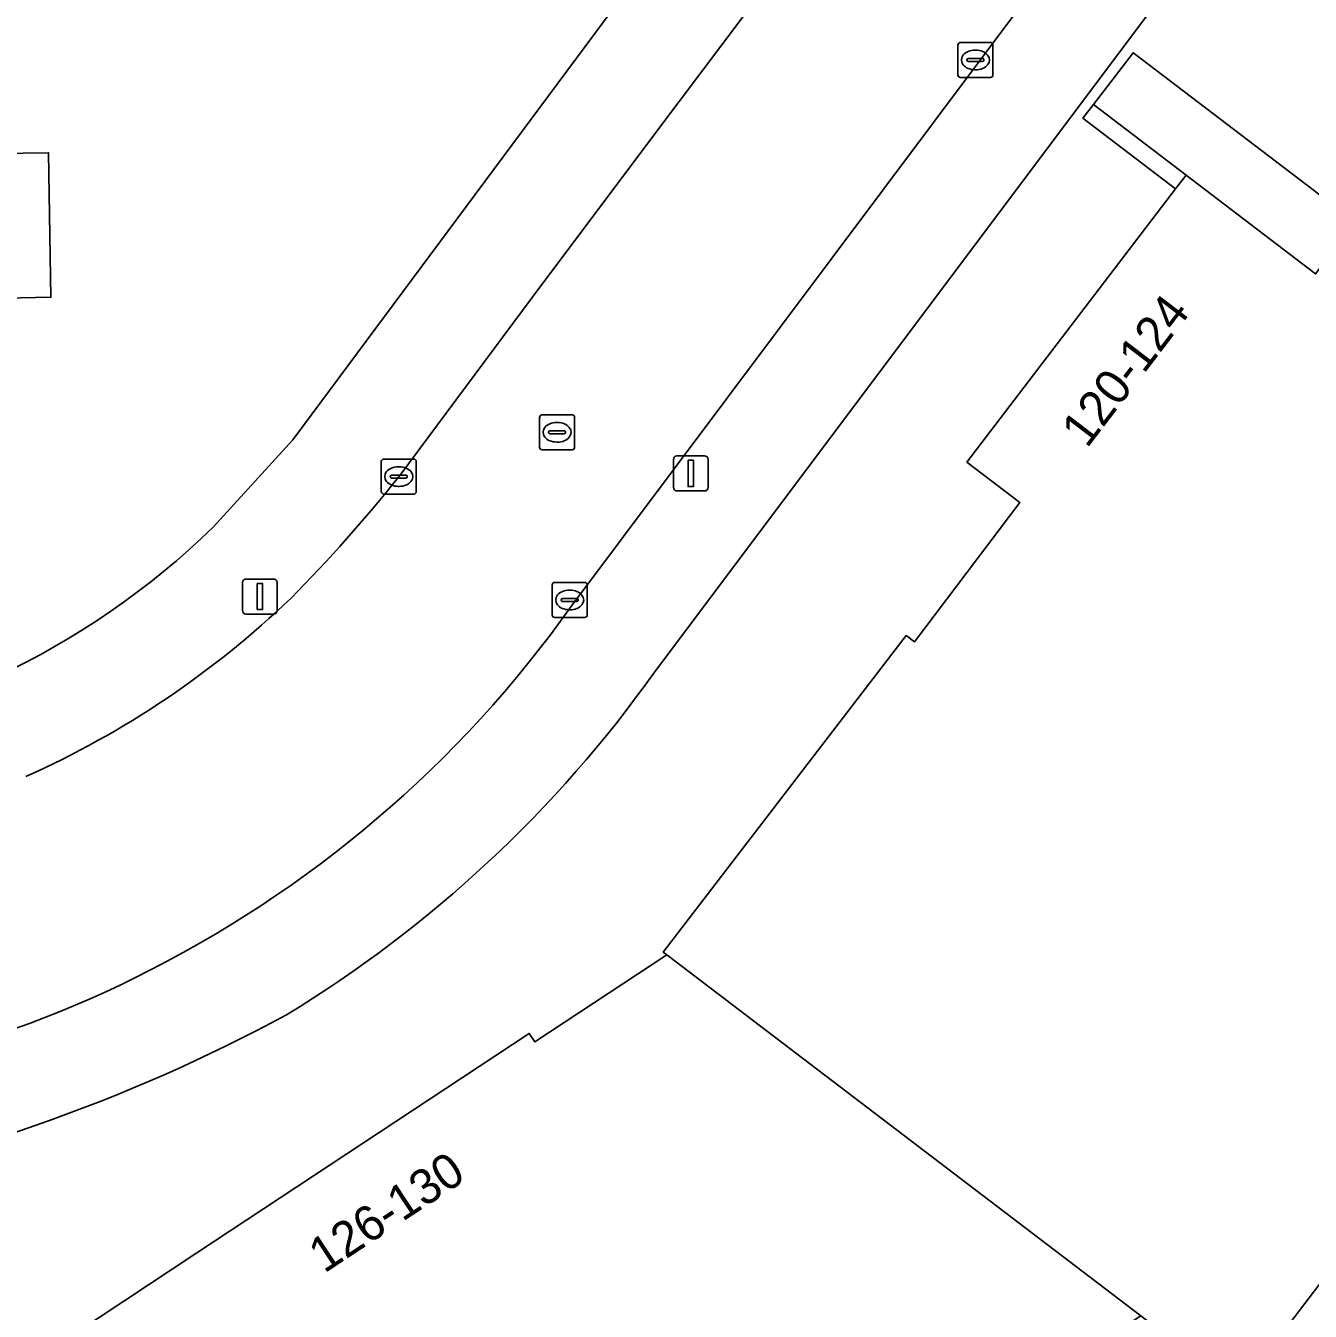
# Model space of a CAD drawing. Extents: x 161139 to 161601, y 381708 to 382245.
# Drawn here: x 161337.13 to 161373.8, y 381862.38 to 381899.09 of the extents above; entities that cross this region are included whole.
import ezdxf

# ---------------------------------------------------------------- set-up
doc = ezdxf.new("R2010")
doc.units = 0
for name, color, linetype in [('IMGEO_Erf', 7, 'Continuous'), ('IMGEO_Groenvoorziening', 7, 'Continuous'), ('IMGEO_Hek', 7, 'Continuous'), ('IMGEO_Kolk', 7, 'Continuous'), ('IMGEO_Lichtmast', 7, 'Continuous'), ('IMGEO_Muur', 7, 'Continuous'), ('IMGEO_Pand', 7, 'Continuous'), ('IMGEO_Pand_nummerreeks', 7, 'Continuous'), ('IMGEO_Rijbaan_lokaal_open', 7, 'Continuous'), ('IMGEO_Rioolput', 7, 'Continuous'), ('IMGEO_Voetpad_op_trap', 7, 'Continuous'), ('IMGEO_Voetpad_open', 7, 'Continuous')]:
    doc.layers.add(name, color=color, linetype=linetype)

msp = doc.modelspace()

# ---------------------------------------------------------------- linework, layer by layer
at = {"layer": 'IMGEO_Erf'}
for points in [[(161342.481, 381884.773), (161344.76, 381887.264), (161354.145, 381899.917), (161371.073, 381922.177)], [(161335.385, 381899.929), (161335.401, 381898.908), (161336.27, 381898.922), (161336.325, 381895.438), (161337.781, 381895.461), (161337.847, 381891.334), (161336.547, 381891.313), (161336.619, 381886.808), (161328.732, 381886.683), (161328.661, 381891.157), (161328.032, 381891.147), (161327.967, 381895.237), (161328.465, 381895.244), (161328.41, 381898.782), (161329.29, 381898.8), (161329.269, 381899.821)]]:
    msp.add_lwpolyline(points, dxfattribs=at)
msp.add_arc((161326.709, 381900.982), 22.616, 275.9879, 314.2183, dxfattribs=at)
at = {"layer": 'IMGEO_Groenvoorziening'}
for points in [[(161382.438, 381917.119), (161355.077, 381880.626)], [(161337.847, 381861.294), (161342.013, 381864.045), (161351.507, 381870.313), (161351.666, 381870.071), (161355.437, 381872.558), (161355.333, 381872.637), (161362.266, 381881.673), (161362.5, 381881.493), (161365.51, 381885.478), (161364, 381886.63), (161369.955, 381894.435), (161367.312, 381896.447), (161367.614, 381896.841), (161368.743, 381898.317), (161368.776, 381898.292), (161375.084, 381893.489)]]:
    msp.add_lwpolyline(points, dxfattribs=at)
for centre, radius, start, end in [((161326.096, 381901.218), 35.552, 301.3226, 324.6045), ((161321.407, 381913.724), 48.737, 279.9868, 298.3875)]:
    msp.add_arc(centre, radius, start, end, dxfattribs=at)
at = {"layer": 'IMGEO_Hek'}
for points in [[(161362.5, 381881.493), (161365.51, 381885.478)], [(161351.666, 381870.071), (161355.437, 381872.558)], [(161337.847, 381861.294), (161342.013, 381864.045)]]:
    msp.add_lwpolyline(points, dxfattribs=at)
at = {"layer": 'IMGEO_Kolk'}
for p, q in [((161363.743, 381897.685), (161363.743, 381898.537)), ((161363.818, 381898.611), (161364.67, 381898.611)), ((161364.231, 381898.391), (161364.256, 381898.391)), ((161364.744, 381898.537), (161364.744, 381897.685)), ((161364.002, 381898.105), (161364.002, 381898.117)), ((161364.44, 381898.068), (161364.042, 381898.068)), ((161364.045, 381898.154), (161364.443, 381898.154)), ((161364.486, 381898.117), (161364.486, 381898.105)), ((161364.67, 381897.611), (161363.818, 381897.611)), ((161364.254, 381897.831), (161364.229, 381897.831)), ((161347.28, 381885.789), (161347.28, 381886.641)), ((161347.355, 381886.715), (161348.207, 381886.715)), ((161348.281, 381886.641), (161348.281, 381885.789)), ((161347.539, 381886.209), (161347.539, 381886.221)), ((161347.582, 381886.258), (161347.98, 381886.258)), ((161347.768, 381886.495), (161347.793, 381886.495)), ((161348.023, 381886.221), (161348.023, 381886.209)), ((161347.977, 381886.172), (161347.579, 381886.172)), ((161347.791, 381885.935), (161347.766, 381885.935)), ((161348.207, 381885.715), (161347.355, 381885.715)), ((161352.16, 381882.266), (161352.16, 381883.118)), ((161352.235, 381883.192), (161353.087, 381883.192)), ((161352.648, 381882.972), (161352.673, 381882.972)), ((161353.161, 381883.118), (161353.161, 381882.266)), ((161352.419, 381882.686), (161352.419, 381882.698)), ((161352.857, 381882.649), (161352.459, 381882.649)), ((161352.462, 381882.735), (161352.86, 381882.735)), ((161352.903, 381882.698), (161352.903, 381882.686)), ((161353.087, 381882.192), (161352.235, 381882.192)), ((161352.671, 381882.412), (161352.646, 381882.412))]:
    msp.add_line(p, q, dxfattribs=at)
for points in [[(161363.743, 381897.685), (161363.743, 381898.537)], [(161363.818, 381898.611), (161364.67, 381898.611)], [(161364.744, 381898.537), (161364.744, 381897.685)], [(161364.67, 381897.611), (161363.818, 381897.611)], [(161347.28, 381885.789), (161347.28, 381886.641)], [(161347.355, 381886.715), (161348.207, 381886.715)], [(161348.281, 381886.641), (161348.281, 381885.789)], [(161348.207, 381885.715), (161347.355, 381885.715)], [(161352.16, 381882.266), (161352.16, 381883.118)], [(161352.235, 381883.192), (161353.087, 381883.192)], [(161353.161, 381883.118), (161353.161, 381882.266)], [(161353.087, 381882.192), (161352.235, 381882.192)]]:
    msp.add_lwpolyline(points, dxfattribs=at)
for centre, radius, start, end in [((161363.82, 381898.535), 0.0765, 91.552, 178.448), ((161363.82, 381898.535), 0.0765, 91.552, 178.448), ((161364.668, 381898.535), 0.0765, 1.552, 88.448), ((161364.668, 381898.535), 0.0765, 1.552, 88.448), ((161364.042, 381898.114), 0.0403, 85.8775, 175.7526), ((161364.039, 381898.104), 0.0366, 178.938, 274.7102), ((161364.443, 381898.111), 0.043, 264.8664, 352.4533), ((161364.447, 381898.116), 0.0386, 1.7309, 96.639), ((161363.82, 381897.687), 0.0765, 181.552, 268.448), ((161363.82, 381897.687), 0.0765, 181.552, 268.448), ((161364.668, 381897.687), 0.0765, 271.552, 358.448), ((161364.668, 381897.687), 0.0765, 271.552, 358.448), ((161347.357, 381886.639), 0.0765, 91.552, 178.448), ((161347.357, 381886.639), 0.0765, 91.552, 178.448), ((161348.205, 381886.639), 0.0765, 1.552, 88.448), ((161348.205, 381886.639), 0.0765, 1.552, 88.448), ((161347.579, 381886.218), 0.0403, 85.8775, 175.7526), ((161347.576, 381886.208), 0.0366, 178.938, 274.7102), ((161347.98, 381886.215), 0.043, 264.8664, 352.4533), ((161347.984, 381886.22), 0.0386, 1.7309, 96.639), ((161347.357, 381885.791), 0.0765, 181.552, 268.448), ((161347.357, 381885.791), 0.0765, 181.552, 268.448), ((161348.205, 381885.791), 0.0765, 271.552, 358.448), ((161348.205, 381885.791), 0.0765, 271.552, 358.448), ((161352.237, 381883.116), 0.0765, 91.552, 178.448), ((161352.237, 381883.116), 0.0765, 91.552, 178.448), ((161353.085, 381883.116), 0.0765, 1.552, 88.448), ((161353.085, 381883.116), 0.0765, 1.552, 88.448), ((161352.459, 381882.695), 0.0403, 85.8775, 175.7526), ((161352.456, 381882.685), 0.0366, 178.938, 274.7102), ((161352.86, 381882.692), 0.043, 264.8664, 352.4533), ((161352.864, 381882.697), 0.0386, 1.7309, 96.639), ((161352.237, 381882.268), 0.0765, 181.552, 268.448), ((161352.237, 381882.268), 0.0765, 181.552, 268.448), ((161353.085, 381882.268), 0.0765, 271.552, 358.448), ((161353.085, 381882.268), 0.0765, 271.552, 358.448)]:
    msp.add_arc(centre, radius, start, end, dxfattribs=at)
for centre, major_axis, ratio, start_param, end_param in [((161364.23, 381898.111), (-0.387, 0.002), 0.722429, 4.712389, 7.853982), ((161364.255, 381898.111), (-0.39, 0.002), 0.717154, 1.570796, 4.712389), ((161347.767, 381886.215), (-0.387, 0.002), 0.722429, 4.712389, 7.853982), ((161347.792, 381886.215), (-0.39, 0.002), 0.717154, 1.570796, 4.712389), ((161352.647, 381882.692), (-0.387, 0.002), 0.722429, 4.712389, 7.853982), ((161352.672, 381882.692), (-0.39, 0.002), 0.717154, 1.570796, 4.712389)]:
    msp.add_ellipse(centre, major_axis=major_axis, ratio=ratio, start_param=start_param, end_param=end_param, dxfattribs=at)
at = {"layer": 'IMGEO_Lichtmast'}
for p, q in [((161355.621, 381885.904), (161355.621, 381886.704)), ((161355.621, 381886.704), (161355.621, 381885.904)), ((161355.721, 381886.804), (161356.511, 381886.804)), ((161356.511, 381886.804), (161355.721, 381886.804)), ((161356.611, 381886.704), (161356.611, 381885.904)), ((161356.611, 381885.904), (161356.611, 381886.704)), ((161356.511, 381885.804), (161355.721, 381885.804)), ((161355.721, 381885.804), (161356.511, 381885.804)), ((161343.418, 381883.29), (161344.208, 381883.29)), ((161344.208, 381883.29), (161343.418, 381883.29)), ((161343.318, 381882.39), (161343.318, 381883.19)), ((161343.318, 381883.19), (161343.318, 381882.39)), ((161344.308, 381883.19), (161344.308, 381882.39)), ((161344.308, 381882.39), (161344.308, 381883.19)), ((161344.208, 381882.29), (161343.418, 381882.29)), ((161343.418, 381882.29), (161344.208, 381882.29))]:
    msp.add_line(p, q, dxfattribs=at)
for points in [[(161356.041, 381886.679), (161356.191, 381886.679), (161356.191, 381885.929), (161356.041, 381885.929), (161356.041, 381886.679)], [(161343.738, 381883.165), (161343.888, 381883.165), (161343.888, 381882.415), (161343.738, 381882.415), (161343.738, 381883.165)]]:
    msp.add_lwpolyline(points, dxfattribs=at)
for centre, start, end in [((161355.721, 381886.704), 90, 180), ((161355.721, 381886.704), 90, 180), ((161356.511, 381886.704), 0, 90), ((161356.511, 381886.704), 360, 90), ((161355.721, 381885.904), 180, 270), ((161355.721, 381885.904), 180, 270), ((161356.511, 381885.904), 270, 0), ((161356.511, 381885.904), 270, 0), ((161343.418, 381883.19), 90, 180), ((161343.418, 381883.19), 90, 180), ((161344.208, 381883.19), 0, 90), ((161344.208, 381883.19), 360, 90), ((161343.418, 381882.39), 180, 270), ((161343.418, 381882.39), 180, 270), ((161344.208, 381882.39), 270, 0), ((161344.208, 381882.39), 270, 0)]:
    msp.add_arc(centre, 0.1, start, end, dxfattribs=at)
at = {"layer": 'IMGEO_Muur'}
msp.add_lwpolyline([(161367.614, 381896.841), (161367.312, 381896.447), (161369.955, 381894.435), (161370.262, 381894.819)], close=True, dxfattribs=at)
at = {"layer": 'IMGEO_Pand'}
msp.add_lwpolyline([(161329.269, 381899.821), (161329.29, 381898.8), (161328.41, 381898.782), (161328.465, 381895.244), (161327.967, 381895.237), (161328.032, 381891.147), (161328.661, 381891.157), (161328.732, 381886.683), (161336.619, 381886.808), (161336.547, 381891.313), (161337.847, 381891.334), (161337.781, 381895.461), (161336.325, 381895.438), (161336.27, 381898.922), (161335.401, 381898.908), (161335.385, 381899.929)], dxfattribs=at)
for points in [[(161390.838, 381885.171), (161376.851, 381895.819), (161375.084, 381893.489), (161373.955, 381892.001), (161370.262, 381894.819), (161369.955, 381894.435), (161364, 381886.63), (161365.51, 381885.478), (161362.5, 381881.493), (161362.266, 381881.673), (161355.333, 381872.637), (161355.437, 381872.558), (161368.964, 381862.254), (161371.759, 381860.122), (161374.079, 381863.168), (161378.602, 381869.107), (161378.802, 381869.369), (161381.677, 381873.144)], [(161355.437, 381872.558), (161351.666, 381870.071), (161351.507, 381870.313), (161342.013, 381864.045), (161337.847, 381861.294), (161342.849, 381853.685), (161345.758, 381855.638), (161346.996, 381856.469), (161350.973, 381850.423), (161353.743, 381852.245), (161360.411, 381856.63), (161368.964, 381862.254)]]:
    msp.add_lwpolyline(points, close=True, dxfattribs=at)
at = {"layer": 'IMGEO_Rijbaan_lokaal_open'}
for points in [[(161375.72, 381923.419), (161374.759, 381922.138), (161373.481, 381920.434), (161368.51, 381913.776), (161358.116, 381900.025), (161357.581, 381899.312), (161355.178, 381896.112), (161351.589, 381891.33), (161347.78, 381886.211)], [(161352.722, 381882.533), (161364.546, 381898.333), (161367.452, 381902.216), (161368.658, 381903.827), (161372.8, 381909.362), (161380.355, 381919.457)], [(161374.394, 381862.928), (161374.079, 381863.168), (161371.759, 381860.122), (161368.964, 381862.254), (161360.411, 381856.63), (161360.621, 381856.311)]]:
    msp.add_lwpolyline(points, dxfattribs=at)
for centre, radius, start, end in [((161314.604, 381912.547), 42.359, 315.2876, 321.5562), ((161326.251, 381901.996), 26.667, 294.0744, 313.7929), ((161325.528, 381901.818), 33.338, 296.193, 324.6578), ((161326.635, 381899.193), 30.495, 268.4215, 296.5025)]:
    msp.add_arc(centre, radius, start, end, dxfattribs=at)
at = {"layer": 'IMGEO_Rioolput'}
for p, q in [((161351.799, 381887.053), (161351.799, 381887.905)), ((161351.874, 381887.979), (161352.726, 381887.979)), ((161352.287, 381887.759), (161352.312, 381887.759)), ((161352.8, 381887.905), (161352.8, 381887.053)), ((161352.058, 381887.473), (161352.058, 381887.485)), ((161352.496, 381887.436), (161352.098, 381887.436)), ((161352.101, 381887.522), (161352.499, 381887.522)), ((161352.542, 381887.485), (161352.542, 381887.473)), ((161352.726, 381886.979), (161351.874, 381886.979)), ((161352.31, 381887.199), (161352.285, 381887.199))]:
    msp.add_line(p, q, dxfattribs=at)
for points in [[(161351.799, 381887.053), (161351.799, 381887.905)], [(161351.874, 381887.979), (161352.726, 381887.979)], [(161352.8, 381887.905), (161352.8, 381887.053)], [(161352.726, 381886.979), (161351.874, 381886.979)]]:
    msp.add_lwpolyline(points, dxfattribs=at)
for centre, radius, start, end in [((161351.876, 381887.903), 0.0765, 91.552, 178.448), ((161351.876, 381887.903), 0.0765, 91.552, 178.448), ((161352.724, 381887.903), 0.0765, 1.552, 88.448), ((161352.724, 381887.903), 0.0765, 1.552, 88.448), ((161352.098, 381887.482), 0.0403, 85.8775, 175.7526), ((161352.095, 381887.472), 0.0366, 178.938, 274.7102), ((161352.499, 381887.479), 0.043, 264.8664, 352.4533), ((161352.503, 381887.484), 0.0386, 1.7309, 96.639), ((161351.876, 381887.055), 0.0765, 181.552, 268.448), ((161351.876, 381887.055), 0.0765, 181.552, 268.448), ((161352.724, 381887.055), 0.0765, 271.552, 358.448), ((161352.724, 381887.055), 0.0765, 271.552, 358.448)]:
    msp.add_arc(centre, radius, start, end, dxfattribs=at)
for centre, major_axis, ratio, start_param, end_param in [((161352.286, 381887.479), (-0.387, 0.002), 0.722429, 4.712389, 7.853982), ((161352.311, 381887.479), (-0.39, 0.002), 0.717154, 1.570796, 4.712389)]:
    msp.add_ellipse(centre, major_axis=major_axis, ratio=ratio, start_param=start_param, end_param=end_param, dxfattribs=at)
at = {"layer": 'IMGEO_Voetpad_op_trap'}
msp.add_lwpolyline([(161368.743, 381898.317), (161367.614, 381896.841), (161370.262, 381894.819), (161373.955, 381892.001), (161375.084, 381893.489), (161368.776, 381898.292)], close=True, dxfattribs=at)
at = {"layer": 'IMGEO_Voetpad_open'}
for points in [[(161372.043, 381923.95), (161371.073, 381922.177), (161354.145, 381899.917), (161344.76, 381887.264), (161342.481, 381884.773)], [(161347.78, 381886.211), (161351.589, 381891.33), (161355.178, 381896.112), (161357.581, 381899.312), (161358.116, 381900.025), (161368.51, 381913.776), (161373.481, 381920.434), (161374.759, 381922.138), (161375.72, 381923.419)], [(161380.355, 381919.457), (161372.8, 381909.362), (161373.53, 381908.815), (161369.388, 381903.281), (161368.658, 381903.827), (161367.452, 381902.216), (161364.546, 381898.333), (161352.722, 381882.533)], [(161355.077, 381880.626), (161382.438, 381917.119)]]:
    msp.add_lwpolyline(points, dxfattribs=at)
for centre, radius, start, end in [((161314.604, 381912.547), 42.359, 315.2876, 321.5562), ((161326.709, 381900.982), 22.616, 275.9879, 314.2183), ((161326.251, 381901.996), 26.667, 294.0744, 313.7929), ((161325.528, 381901.818), 33.338, 296.193, 324.6578), ((161326.096, 381901.218), 35.552, 301.3226, 324.6045), ((161326.635, 381899.193), 30.495, 268.4215, 296.5025), ((161321.407, 381913.724), 48.737, 279.9868, 298.3875)]:
    msp.add_arc(centre, radius, start, end, dxfattribs=at)

# ---------------------------------------------------------------- texts
at = {"layer": 'IMGEO_Pand_nummerreeks'}
for s, rotation, p in [('120-124', 52.6548, (161367.426, 381886.999)), ('126-130', 33.4321, (161345.649, 381863.45))]:
    msp.add_text(s, height=1, rotation=rotation, dxfattribs=at).set_placement(p)

doc.saveas('drawing.dxf')
